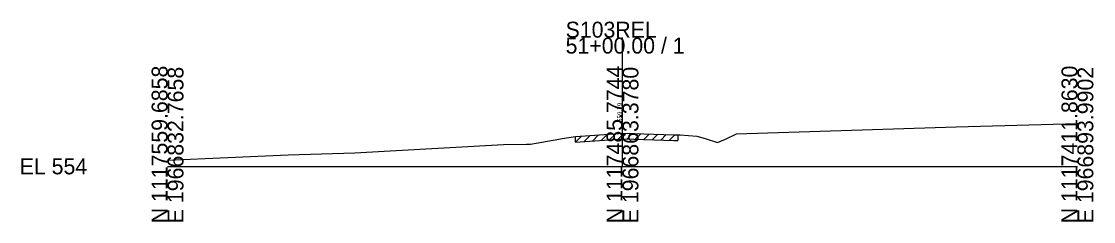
# Model space of a CAD drawing. Extents: x -26 to 163, y -10 to 24518.
# Drawn here: x -25.7 to 162.8, y 1490.3 to 1525.5 of the extents above; entities that cross this region are included whole.
import ezdxf

# ---------------------------------------------------------------- set-up
doc = ezdxf.new("R2010")
doc.units = 0
for name, color, linetype in [('RD_GPK_XS_Cell', 7, 'Continuous'), ('RD_XS_ExGround', 7, 'Continuous'), ('RD_XS_ExPaveRet', 7, 'Continuous'), ('RD_XS_TX_Elev_EX', 7, 'Continuous')]:
    doc.layers.add(name, color=color, linetype=linetype)

msp = doc.modelspace()

# ---------------------------------------------------------------- linework, layer by layer
at = {"layer": 'RD_GPK_XS_Cell'}
for p, q in [((80, 1500), (80, 1522.61)), ((0, 1500), (80, 1500)), ((80, 1500), (160, 1500))]:
    msp.add_line(p, q, dxfattribs=at)
at = {"layer": 'RD_XS_ExGround'}
msp.add_lwpolyline([(0, 1501.09), (21.24, 1502), (32.96, 1502.38), (39.12, 1502.72), (59.1, 1503.85), (63.15, 1503.9), (63.83, 1503.91), (68.81, 1504.78), (69.4, 1504.87), (71.74, 1505.26), (72.56, 1505.31), (80.25, 1505.81), (89.05, 1505.56), (89.73, 1505.54), (90.12, 1505.51), (93.07, 1505.32), (94.54, 1504.92), (96.69, 1504.19), (98.11, 1504.75), (100.08, 1505.71), (138.67, 1506.93), (160, 1507.54)], dxfattribs=at)
at = {"layer": 'RD_XS_ExPaveRet'}
for p, q in [((71.74, 1504.26), (72.81, 1505.33)), ((71.74, 1504.26), (71.74, 1505.26)), ((72.56, 1504.31), (80.25, 1504.81)), ((73.24, 1504.36), (74.31, 1505.43)), ((74.74, 1504.45), (75.81, 1505.52)), ((76.24, 1504.55), (77.31, 1505.62)), ((77.74, 1504.65), (78.81, 1505.72)), ((79.24, 1504.75), (80.31, 1505.81)), ((80.25, 1504.81), (89.05, 1504.56)), ((80.74, 1504.8), (81.71, 1505.77)), ((82.24, 1504.75), (83.21, 1505.73)), ((83.74, 1504.71), (84.71, 1505.68)), ((85.24, 1504.67), (86.21, 1505.64)), ((86.74, 1504.62), (87.71, 1505.6)), ((88.24, 1504.58), (89.21, 1505.55)), ((89.05, 1504.56), (89.73, 1504.54)), ((89.73, 1505.54), (89.73, 1504.54)), ((71.74, 1504.26), (72.56, 1504.31))]:
    msp.add_line(p, q, dxfattribs=at)

# ---------------------------------------------------------------- texts
at = {"layer": 'RD_GPK_XS_Cell'}
for s, p in [('S103REL', (70, 1522.61)), ('51+00.00 / 1', (70, 1519.81)), ('EL 554', (-26, 1498.6))]:
    msp.add_text(s, height=2.8, dxfattribs=at).set_placement(p)
for s, p in [('N 1117559.6858', (0, 1490)), ('E 1966832.7658', (2.8, 1490)), ('N 1117485.7744', (80, 1490)), ('E 1966863.3780', (82.8, 1490)), ('N 1117411.8630', (160, 1490)), ('E 1966893.9902', (162.8, 1490))]:
    msp.add_text(s, height=2.8, rotation=90, dxfattribs=at).set_placement(p)
at = {"layer": 'RD_XS_TX_Elev_EX'}
msp.add_text('559.79', height=0.8, rotation=90, dxfattribs=at).set_placement((79.9, 1507.79))

doc.saveas('drawing.dxf')
